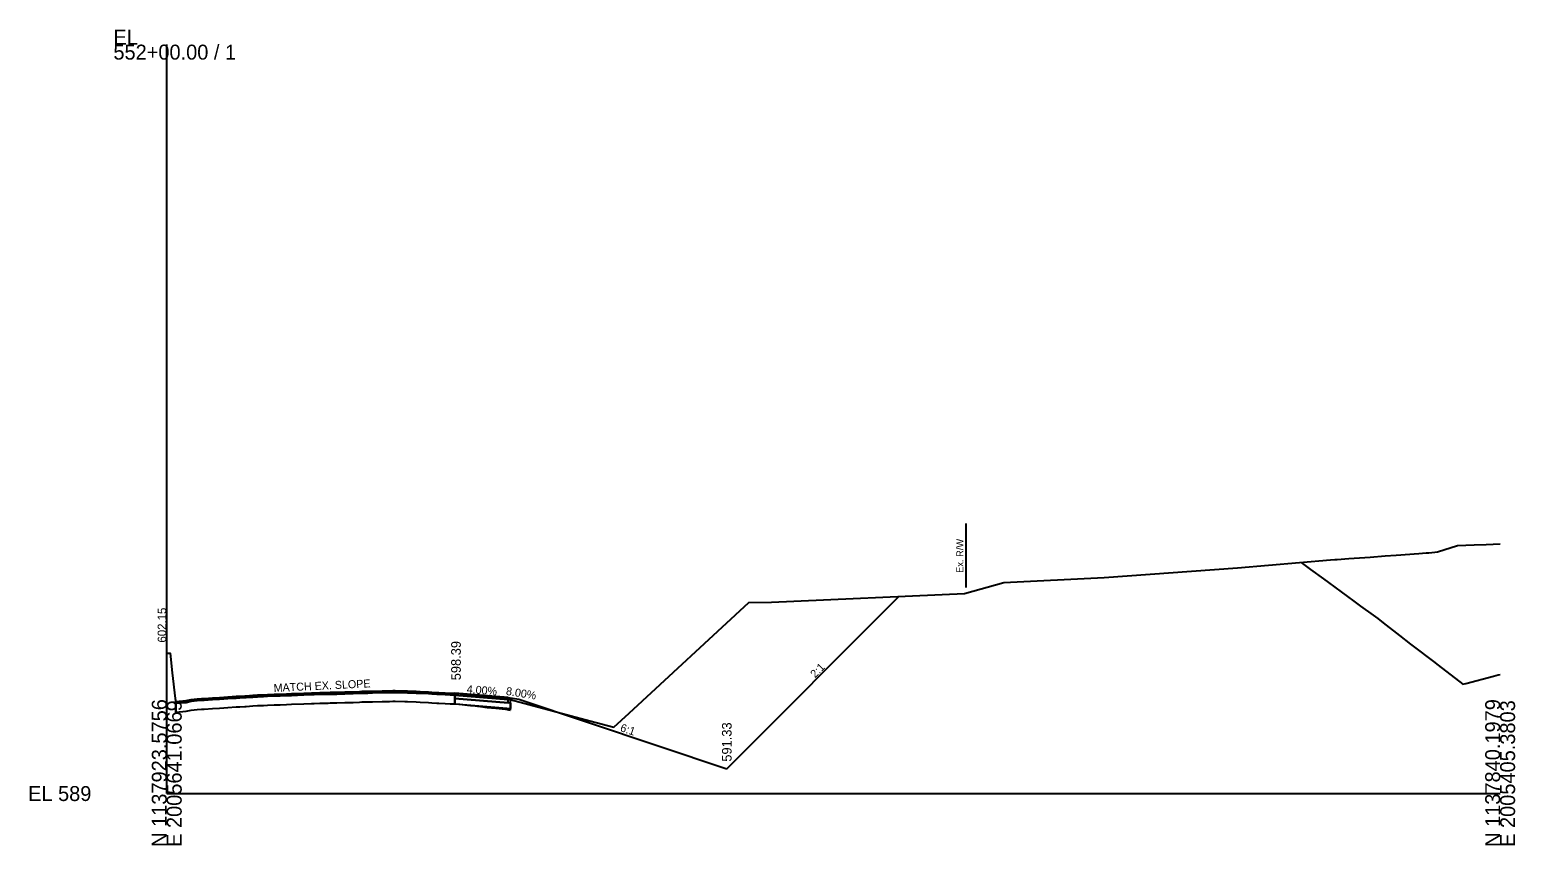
# Model space of a CAD drawing. Extents: x -201 to 2007062, y -213 to 1139737.
# Drawn here: x -25.7 to 252.8, y 6990.3 to 7143.1 of the extents above; entities that cross this region are included whole.
import ezdxf

# ---------------------------------------------------------------- set-up
doc = ezdxf.new("R2010")
doc.units = 0
for name, color, linetype in [('Default', 7, 'Continuous'), ('RD_DTM_Design_FG', 7, 'Continuous'), ('RD_GPK_XS_Cell', 7, 'Continuous'), ('RD_Sketch1', 7, 'Continuous'), ('RD_XS_Base', 7, 'Continuous'), ('RD_XS_EarthShd', 7, 'Continuous'), ('RD_XS_ExGround', 7, 'Continuous'), ('RD_XS_ExPaveRet', 7, 'Continuous'), ('RD_XS_ExRW', 7, 'Continuous'), ('RD_XS_PaveOvlay', 7, 'Continuous'), ('RD_XS_PaveShd', 7, 'Continuous'), ('RD_XS_TieSlope', 7, 'Continuous'), ('RD_XS_TX_Ditch', 7, 'Continuous'), ('RD_XS_TX_Elev_EX', 7, 'Continuous'), ('RD_XS_TX_Elev_PR', 7, 'Continuous'), ('RD_XS_TX_Slope', 7, 'Continuous')]:
    doc.layers.add(name, color=color, linetype=linetype)

msp = doc.modelspace()

# ---------------------------------------------------------------- linework, layer by layer
at = {"layer": 'RD_DTM_Design_FG'}
msp.add_lwpolyline([(212.67, 7043.31), (214.44, 7042.01), (216.87, 7040.22), (217.79, 7039.55), (222.58, 7036.05), (223.84, 7035.13), (226.18, 7033.43), (227.04, 7032.77), (228.05, 7031.99), (231.15, 7029.62), (233.22, 7028.02), (233.72, 7027.64), (237.52, 7024.72), (238.39, 7024.06), (243.03, 7020.49), (243.56, 7020.63), (248.73, 7021.98), (249.63, 7022.22), (250, 7022.32)], dxfattribs=at)
at = {"layer": 'RD_GPK_XS_Cell'}
for q in [(0, 7140.33), (250, 7000)]:
    msp.add_line((0, 7000), q, dxfattribs=at)
at = {"layer": 'RD_XS_Base'}
for points in [[(64, 7017.65), (54, 7018.45)], [(54, 7018.45), (54, 7017.79)], [(64.5, 7016.95), (64, 7016.99), (54, 7017.79)], [(54, 7017.79), (54, 7016.79)], [(54, 7017.79), (64, 7016.99)], [(54, 7016.79), (64.5, 7015.95)], [(64, 7016.99), (64, 7017.65)], [(64.5, 7015.95), (64.5, 7016.95)]]:
    msp.add_lwpolyline(points, dxfattribs=at)
at = {"layer": 'RD_XS_EarthShd'}
msp.add_lwpolyline([(64, 7017.98), (66, 7017.66)], dxfattribs=at)
at = {"layer": 'RD_XS_ExGround'}
msp.add_lwpolyline([(0, 7026.29), (0.63, 7026.31), (1.03, 7022.65), (1.55, 7017.79), (1.73, 7017.27), (3.64, 7017.42), (4.58, 7017.63), (5.73, 7017.76), (6.52, 7017.81), (7.02, 7017.84), (8.56, 7017.94), (9.91, 7018.02), (10.68, 7018.07), (11.47, 7018.13), (13.04, 7018.22), (13.72, 7018.26), (14.61, 7018.32), (14.92, 7018.34), (16.17, 7018.42), (17.04, 7018.47), (17.44, 7018.49), (18.15, 7018.52), (18.91, 7018.56), (20.15, 7018.62), (20.88, 7018.62), (21.29, 7018.64), (22.44, 7018.69), (23.41, 7018.73), (25.71, 7018.81), (27.14, 7018.87), (27.65, 7018.89), (28.71, 7018.94), (30.28, 7018.94), (30.67, 7018.97), (31.89, 7018.98), (33.41, 7019.05), (34.01, 7019.06), (34.98, 7019.09), (36.14, 7019.15), (36.55, 7019.16), (37.71, 7019.17), (38.26, 7019.18), (38.56, 7019.19), (40.38, 7019.25), (41.25, 7019.27), (41.78, 7019.27), (42.42, 7019.28), (42.85, 7019.28), (44.62, 7019.25), (45.12, 7019.23), (46.74, 7019.16), (47.52, 7019.13), (49.08, 7019.06), (49.7, 7019.02), (50.65, 7018.96), (50.99, 7018.95), (52.22, 7018.89), (53.11, 7018.83), (53.95, 7018.78), (54.97, 7018.73), (55.39, 7018.68), (56.37, 7018.57), (56.92, 7018.52), (57.35, 7018.49), (58.26, 7018.38), (58.83, 7018.33), (60.05, 7018.13), (61.69, 7018.01), (63.54, 7017.83), (64.4, 7017.62), (79.3, 7013.61), (83.85, 7012.41), (86.69, 7015.06), (109.13, 7035.77), (113.37, 7035.84), (149.56, 7037.47), (156.95, 7039.52), (175.73, 7040.49), (200.75, 7042.3), (218.2, 7043.78), (219.03, 7043.84), (219.44, 7043.87), (221.63, 7044.03), (225.61, 7044.32), (228.43, 7044.53), (230.48, 7044.68), (234.78, 7044.99), (236.1, 7045.09), (236.65, 7045.13), (237.18, 7045.17), (237.74, 7045.24), (238.28, 7045.32), (242.03, 7046.5), (245.15, 7046.62), (247.41, 7046.69), (250, 7046.78)], dxfattribs=at)
at = {"layer": 'RD_XS_ExPaveRet'}
for p, q in [((1.73, 7015.27), (1.73, 7017.27)), ((1.73, 7016.93), (1.73, 7015.27)), ((13.04, 7016.22), (13.72, 7016.26)), ((13.04, 7016.22), (13.72, 7016.26)), ((13.72, 7016.26), (14.61, 7016.32)), ((13.72, 7016.26), (14.61, 7016.32)), ((14.61, 7016.32), (14.92, 7016.34)), ((14.61, 7016.32), (14.92, 7016.34)), ((14.92, 7016.34), (16.17, 7016.42)), ((14.92, 7016.34), (16.17, 7016.42)), ((16.17, 7016.42), (17.04, 7016.47)), ((16.17, 7016.42), (17.04, 7016.47)), ((17.04, 7016.47), (17.44, 7016.49)), ((17.04, 7016.47), (17.44, 7016.49)), ((17.44, 7016.49), (18.15, 7016.52)), ((17.44, 7016.49), (18.15, 7016.52)), ((18.15, 7016.52), (18.91, 7016.56)), ((18.15, 7016.52), (18.91, 7016.56)), ((18.91, 7016.56), (20.15, 7016.62)), ((18.91, 7016.56), (20.15, 7016.62)), ((20.15, 7016.62), (20.88, 7016.62)), ((20.15, 7016.62), (20.88, 7016.62)), ((20.88, 7016.62), (21.29, 7016.64)), ((20.88, 7016.62), (21.29, 7016.64)), ((21.29, 7016.64), (22.44, 7016.69)), ((21.29, 7016.64), (22.44, 7016.69)), ((22.44, 7016.69), (23.41, 7016.73)), ((22.44, 7016.69), (23.41, 7016.73)), ((23.41, 7016.73), (25.71, 7016.81)), ((23.41, 7016.73), (25.71, 7016.81)), ((25.71, 7016.81), (27.14, 7016.87)), ((25.71, 7016.81), (27.14, 7016.87)), ((27.14, 7016.87), (27.65, 7016.89)), ((27.14, 7016.87), (27.65, 7016.89)), ((27.65, 7016.89), (28.71, 7016.94)), ((27.65, 7016.89), (28.71, 7016.94)), ((28.71, 7016.94), (30.28, 7016.94)), ((28.71, 7016.94), (30.28, 7016.94)), ((30.28, 7016.94), (30.67, 7016.97)), ((30.28, 7016.94), (30.67, 7016.97)), ((30.67, 7016.97), (31.89, 7016.98)), ((30.67, 7016.97), (31.89, 7016.98)), ((31.89, 7016.98), (33.41, 7017.05)), ((31.89, 7016.98), (33.41, 7017.05)), ((33.41, 7017.05), (34.01, 7017.06)), ((33.41, 7017.05), (34.01, 7017.06)), ((34.01, 7017.06), (34.98, 7017.09)), ((34.01, 7017.06), (34.98, 7017.09)), ((34.98, 7017.09), (36.14, 7017.15)), ((34.98, 7017.09), (36.14, 7017.15)), ((36.14, 7017.15), (36.55, 7017.16)), ((36.14, 7017.15), (36.55, 7017.16)), ((36.55, 7017.16), (37.71, 7017.17)), ((36.55, 7017.16), (37.71, 7017.17)), ((37.71, 7017.17), (38.26, 7017.18)), ((37.71, 7017.17), (38.26, 7017.18)), ((38.26, 7017.18), (38.56, 7017.19)), ((38.26, 7017.18), (38.56, 7017.19)), ((38.56, 7017.19), (40.38, 7017.25)), ((38.56, 7017.19), (40.38, 7017.25)), ((40.38, 7017.25), (41.25, 7017.27)), ((40.38, 7017.25), (41.25, 7017.27)), ((41.25, 7017.27), (41.78, 7017.27)), ((41.25, 7017.27), (41.78, 7017.27)), ((41.78, 7017.27), (42.42, 7017.28)), ((41.78, 7017.27), (42.42, 7017.28)), ((42.42, 7017.28), (42.85, 7017.28)), ((42.42, 7017.28), (42.85, 7017.28)), ((42.85, 7017.28), (44.62, 7017.25)), ((42.85, 7017.28), (44.62, 7017.25)), ((44.62, 7017.25), (45.12, 7017.23)), ((44.62, 7017.25), (45.12, 7017.23)), ((45.12, 7017.23), (46.74, 7017.16)), ((45.12, 7017.23), (46.74, 7017.16)), ((46.74, 7017.16), (47.52, 7017.13)), ((46.74, 7017.16), (47.52, 7017.13)), ((47.52, 7017.13), (49.08, 7017.06)), ((47.52, 7017.13), (49.08, 7017.06)), ((49.08, 7017.06), (49.7, 7017.02)), ((49.08, 7017.06), (49.7, 7017.02)), ((49.7, 7017.02), (50.65, 7016.96)), ((49.7, 7017.02), (50.65, 7016.96)), ((50.65, 7016.96), (50.99, 7016.95)), ((50.65, 7016.96), (50.99, 7016.95)), ((50.99, 7016.95), (52.22, 7016.89)), ((50.99, 7016.95), (52.22, 7016.89)), ((52.22, 7016.89), (53.11, 7016.83)), ((52.22, 7016.89), (53.11, 7016.83)), ((53.11, 7016.83), (53.95, 7016.78)), ((53.11, 7016.83), (53.95, 7016.78)), ((53.95, 7016.78), (54.97, 7016.73)), ((53.95, 7016.78), (54, 7016.78)), ((54, 7017.79), (54, 7018.45)), ((54, 7018.45), (54, 7018.45)), ((54, 7016.79), (54, 7017.79)), ((54, 7016.79), (54, 7016.78)), ((54, 7016.78), (54, 7016.79)), ((54.97, 7016.73), (55.39, 7016.68)), ((55.39, 7016.68), (56.37, 7016.57)), ((56.37, 7016.57), (56.92, 7016.52)), ((56.92, 7016.52), (57.35, 7016.49)), ((57.35, 7016.49), (58.26, 7016.38)), ((58.26, 7016.38), (58.83, 7016.33)), ((58.83, 7016.33), (60.05, 7016.13)), ((64.4, 7017.62), (64.4, 7015.62)), ((1.73, 7015.27), (3.64, 7015.42)), ((1.73, 7015.27), (3.64, 7015.42)), ((3.64, 7015.42), (4.58, 7015.63)), ((3.64, 7015.42), (4.58, 7015.63)), ((4.58, 7015.63), (5.73, 7015.76)), ((4.58, 7015.63), (5.73, 7015.76)), ((5.73, 7015.76), (6.52, 7015.81)), ((5.73, 7015.76), (6.52, 7015.81)), ((6.52, 7015.81), (7.02, 7015.84)), ((6.52, 7015.81), (7.02, 7015.84)), ((7.02, 7015.84), (8.56, 7015.94)), ((7.02, 7015.84), (8.56, 7015.94)), ((8.56, 7015.94), (9.91, 7016.02)), ((8.56, 7015.94), (9.91, 7016.02)), ((9.91, 7016.02), (10.68, 7016.07)), ((9.91, 7016.02), (10.68, 7016.07)), ((10.68, 7016.07), (11.47, 7016.13)), ((10.68, 7016.07), (11.47, 7016.13)), ((11.47, 7016.13), (13.04, 7016.22)), ((11.47, 7016.13), (13.04, 7016.22)), ((60.05, 7016.13), (61.69, 7016.01)), ((61.69, 7016.01), (63.54, 7015.83)), ((63.54, 7015.83), (64.4, 7015.62)), ((64.4, 7015.62), (64.4, 7015.62))]:
    msp.add_line(p, q, dxfattribs=at)
for points in [[(54, 7018.45), (53.95, 7018.45), (53.11, 7018.5), (52.22, 7018.56), (50.99, 7018.61), (50.65, 7018.63), (49.7, 7018.69), (49.08, 7018.73), (47.52, 7018.8), (46.74, 7018.83), (45.12, 7018.89), (44.62, 7018.91), (42.85, 7018.95), (42.42, 7018.94), (41.78, 7018.94), (41.25, 7018.94), (40.38, 7018.92), (38.56, 7018.86), (38.26, 7018.85), (37.71, 7018.84), (36.55, 7018.83), (36.14, 7018.81), (34.98, 7018.76), (34.01, 7018.73), (33.41, 7018.71), (31.89, 7018.65), (30.67, 7018.64), (30.28, 7018.61), (28.71, 7018.61), (27.65, 7018.55), (27.14, 7018.53), (25.71, 7018.48), (23.41, 7018.39), (22.44, 7018.36), (21.29, 7018.31), (20.88, 7018.29), (20.15, 7018.28), (18.91, 7018.23), (18.15, 7018.19), (17.44, 7018.16), (17.04, 7018.14), (16.17, 7018.09), (14.92, 7018.01), (14.61, 7017.99), (13.72, 7017.93), (13.04, 7017.89), (11.47, 7017.79), (10.68, 7017.74), (9.91, 7017.69), (8.56, 7017.6), (7.02, 7017.51), (6.52, 7017.48), (5.73, 7017.43), (4.58, 7017.3), (3.64, 7017.08), (1.73, 7016.93)], [(1.73, 7016.93), (1.73, 7016.93)]]:
    msp.add_lwpolyline(points, dxfattribs=at)
at = {"layer": 'RD_XS_ExRW'}
msp.add_line((149.85, 7050.59), (149.85, 7038.59), dxfattribs=at)
at = {"layer": 'RD_XS_PaveOvlay'}
for points in [[(1.73, 7017.27), (3.64, 7017.42), (4.58, 7017.63), (5.73, 7017.76), (6.52, 7017.81), (7.02, 7017.84), (8.56, 7017.94), (9.91, 7018.02), (10.68, 7018.07), (11.47, 7018.13), (13.04, 7018.22), (13.72, 7018.26), (14.61, 7018.32), (14.92, 7018.34), (16.17, 7018.42), (17.04, 7018.47), (17.44, 7018.49), (18.15, 7018.52), (18.91, 7018.56), (20.15, 7018.62), (20.88, 7018.62), (21.29, 7018.64), (22.44, 7018.69), (23.41, 7018.73), (25.71, 7018.81), (27.14, 7018.87), (27.65, 7018.89), (28.71, 7018.94), (30.28, 7018.94), (30.67, 7018.97), (31.89, 7018.98), (33.41, 7019.05), (34.01, 7019.06), (34.98, 7019.09), (36.14, 7019.15), (36.55, 7019.16), (37.71, 7019.17), (38.26, 7019.18), (38.56, 7019.19), (40.38, 7019.25), (41.25, 7019.27), (41.78, 7019.27), (42.42, 7019.28), (42.85, 7019.28), (44.62, 7019.25), (45.12, 7019.23), (46.74, 7019.16), (47.52, 7019.13), (49.08, 7019.06), (49.7, 7019.02), (50.65, 7018.96), (50.99, 7018.95), (52.22, 7018.89), (53.11, 7018.83), (53.95, 7018.78), (54, 7018.78)], [(1.73, 7016.93), (3.64, 7017.08), (4.58, 7017.3), (5.73, 7017.43), (6.52, 7017.48), (7.02, 7017.51), (8.56, 7017.6), (9.91, 7017.69), (10.68, 7017.74), (11.47, 7017.79), (13.04, 7017.89), (13.72, 7017.93), (14.61, 7017.99), (14.92, 7018.01), (16.17, 7018.09), (17.04, 7018.14), (17.44, 7018.16), (18.15, 7018.19), (18.91, 7018.23), (20.15, 7018.28), (20.88, 7018.29), (21.29, 7018.31), (22.44, 7018.36), (23.41, 7018.39), (25.71, 7018.48), (27.14, 7018.53), (27.65, 7018.55), (28.71, 7018.61), (30.28, 7018.61), (30.67, 7018.64), (31.89, 7018.65), (33.41, 7018.71), (34.01, 7018.73), (34.98, 7018.76), (36.14, 7018.81), (36.55, 7018.83), (37.71, 7018.84), (38.26, 7018.85), (38.56, 7018.86), (40.38, 7018.92), (41.25, 7018.94), (41.78, 7018.94), (42.42, 7018.94), (42.85, 7018.95), (44.62, 7018.91), (45.12, 7018.89), (46.74, 7018.83), (47.52, 7018.8), (49.08, 7018.73), (49.7, 7018.69), (50.65, 7018.63), (50.99, 7018.61), (52.22, 7018.56), (53.11, 7018.5), (53.95, 7018.45), (54, 7018.45)]]:
    msp.add_lwpolyline(points, dxfattribs=at)
at = {"layer": 'RD_XS_PaveShd'}
for points in [[(64, 7017.98), (54, 7018.78)], [(54, 7018.78), (54, 7018.45)], [(54, 7018.45), (64, 7017.65)], [(64, 7017.65), (64, 7017.98)]]:
    msp.add_lwpolyline(points, dxfattribs=at)
at = {"layer": 'RD_XS_TieSlope'}
msp.add_line((66, 7017.66), (105, 7004.66), dxfattribs=at)
msp.add_lwpolyline([(105, 7004.66), (137.25, 7036.91)], dxfattribs=at)

# ---------------------------------------------------------------- texts
at = {"layer": 'Default'}
msp.add_text('-', height=0.0001, dxfattribs=at).set_placement((0, 7000))
at = {"layer": 'RD_GPK_XS_Cell'}
for s, p in [('EL', (-10, 7140.33)), ('552+00.00 / 1', (-10, 7137.53)), ('EL 589', (-26, 6998.6))]:
    msp.add_text(s, height=2.8, dxfattribs=at).set_placement(p)
for s, p in [('N 1137923.5756', (0, 6990)), ('E 2005641.0669', (2.8, 6990)), ('N 1137840.1979', (250, 6990)), ('E 2005405.3803', (252.8, 6990))]:
    msp.add_text(s, height=2.8, rotation=90, dxfattribs=at).set_placement(p)
at = {"layer": 'RD_Sketch1'}
for s, p in [('Exterior Boundary', (135.65, 7036.81)), ('LOC_C', (135.98, 7036.81)), ('Exterior Boundary', (53.44, 7018.73)), ('EP_X_R', (53.73, 7018.73)), ('EP_X2', (53.79, 7017.74)), ('EP_X3', (53.79, 7016.74)), ('EP_X1', (53.8, 7018.4)), ('ESP1_R', (63.73, 7017.6)), ('ESP2_R', (63.73, 7016.94)), ('ESP_R', (63.77, 7017.93)), ('ESP4_R', (64.23, 7016.9)), ('ES_R', (65.82, 7017.61)), ('ESP3_R', (64.23, 7015.9))]:
    msp.add_text(s, height=0.05, dxfattribs=at).set_placement(p)
at = {"layer": 'RD_XS_ExRW'}
msp.add_text('Ex. R/W ', height=1.3, rotation=90, dxfattribs=at).set_placement((149.35, 7041.35))
at = {"layer": 'RD_XS_TX_Ditch'}
msp.add_text('591.33', height=1.8, rotation=90, dxfattribs=at).set_placement((105.9, 7005.97))
at = {"layer": 'RD_XS_TX_Elev_EX'}
msp.add_text('602.15', height=1.6, rotation=90, dxfattribs=at).set_placement((-0.1, 7028.29))
at = {"layer": 'RD_XS_TX_Elev_PR'}
msp.add_text('598.39', height=1.8, rotation=90, dxfattribs=at).set_placement((55.13, 7021.22))
at = {"layer": 'RD_XS_TX_Slope'}
for s, rotation, p in [('2:1', 45, (121.56, 7021.57)), ('MATCH EX. SLOPE', 2.7318, (20.08, 7019.04)), ('4.00%', 355.4261, (56.2, 7018.85)), ('8.00%', 350.9097, (63.53, 7018.51)), ('6:1', 341.5651, (84.9, 7011.72))]:
    msp.add_text(s, height=1.5, rotation=rotation, dxfattribs=at).set_placement(p)

doc.saveas('drawing.dxf')
